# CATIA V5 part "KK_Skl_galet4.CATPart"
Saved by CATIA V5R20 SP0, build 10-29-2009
Part number: Skl_galet4
Publications: "Axe_pivot_galet4", "Plan.Ref5", "Point.2", "Plan_Ref1"
Bounding box of the stored display mesh (mm): x -7.5 to 32.5, y 235 to 235, z -15 to -15
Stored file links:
  G:\Khaled_CFAO_2011\ST2M\ST2M_GR2\aandujar\Khaled\CAD_thinkMOTION\KK_Skl_galet4.CATPart
  G:\Khaled_CFAO_2011\ST2M\ST2M_GR2\aandujar\Khaled\CAD_thinkMOTION\KK_Skl_scie_mecanique.CATProduct
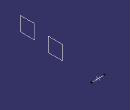
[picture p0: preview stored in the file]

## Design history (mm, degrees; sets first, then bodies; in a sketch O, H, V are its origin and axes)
WSupportSet1: ActiveGrid {3dwsupport RefPoint {point stored without definition}, 3DWOS ({wsupport Support xy-plane, RefPoint {3dwsupport}, GridIn {cartgrid Value 100, Stepbid1 0, Value 100, Stepbid2 0, Direction (1, 0, 0)}, GeometricData ({line type PtDir, Direction (1, 0, 0), Support xy-plane}; {line type PtDir, Direction (0, 1, 0), Support yz-plane})}; {wsupport Support yz-plane, RefPoint {3dwsupport}, GridIn {cartgrid Value 100, Stepbid1 0, Value 100, Stepbid2 0, Direction (0, 1, 0)}, GeometricData ({line type PtDir, Direction (0, 1, 0), Support yz-plane}; {line type PtDir, Direction (0, 0, 1), Support zx-plane})}; {wsupport Support zx-plane, RefPoint {3dwsupport}, GridIn {cartgrid Value 100, Stepbid1 0, Value 100, Stepbid2 0, Direction (0, 0, 1)}, GeometricData ({line type PtDir, Direction (0, 0, 1), Support zx-plane}; {line type PtDir, Direction (1, 0, 0), Support xy-plane})}), GeometricData ({line type PtDir, RefPoint {point stored without definition}, Direction (1, 0, 0), Support xy-plane}; {line type PtDir, RefPoint {point stored without definition}, Direction (0, 1, 0), Support yz-plane}; {line type PtDir, RefPoint {point stored without definition}, Direction (0, 0, 1), Support zx-plane})}
Set1
  Line1 "Axe_pivot_galet4": type Normal, RefPoint Point1, RefSkin Plane2, Start -20, End 20
Set2
  Plane1 "Plan.Ref5": linked copy from another document
  Point1: linked copy from another document
  Plane2 "Plan_Ref1": linked copy from another document
Body1 (main body)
